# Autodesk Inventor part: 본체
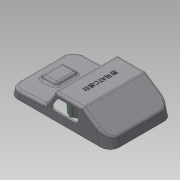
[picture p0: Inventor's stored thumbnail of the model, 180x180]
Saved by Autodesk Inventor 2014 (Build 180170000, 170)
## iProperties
Created: 2015-05
Part Number: 본체
Material: Generic
Document SubType Name: Modeling
Designer: Administrator
Density: 1 g/cm^3
Appearance: Default
Author: Administrator
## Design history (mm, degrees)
sketch "스케치1"
  geometry: L1 (61, 0)-(-61, 0); L2 (-61, 0)-(-58.321, 10); L3 (-58.321, 10)-(-28.321, 30); L4 (-28.321, 30)-(4.842, 30); L5 (61, 0)-(58.588, 9); L6 (58.588, 9)-(16.588, 11.201); L7 (4.842, 30)-(16.588, 11.201); 2 further points
  constraints: 14 end point, 1 coincident, 1 horizontal, 1 midpoint, 1 parallel
  dimensions: "d0" = 122 distance of L1.start L1.end; "d1" = 105 deg angle of L1 L2; "d2" = 20 vertical distance of L2.end L3.end; "d3" = 30 vertical distance of L1.end L3.end; "d4" = 30 horizontal distance of L2.end L3.end; "d5" = 9 vertical distance of L1.start L5.end; "d6" = 105 deg angle of L1 L5; "d7" = 3 deg angle of L1 L6; "d8" = 42 horizontal distance of L5.end L6.end; "d9" = 125 deg angle of L6 L7
extrude "돌출1" new body sketch "스케치1" stored distance "d10" = 76; taper "d11" = 0 deg
sketch "스케치2"
  geometry: L1 (58.588, 9)-(16.588, 11.201) reference; L2 (47.588, 9.576)-(46.236, 14); L3 (27.588, 10.625)-(29.021, 14); L4 (46.236, 14)-(29.021, 14); 1 further point
  constraints: 6 end point, 2 point on line
  dimensions: "d12" = 5 vertical distance of L2.end L1.start; "d13" = 11 horizontal distance of L2.start L1.start; "d14" = 20 horizontal distance of L3.start L2.start; "d15" = 70 deg angle of L1 L3; "d16" = 70 deg angle of L1 L2; "d17" = 5 vertical distance of L1.start L3.end
extrude "돌출2" join sketch "스케치2" stored distance "d18" = 26; taper "d19" = 0 deg
fillet "모깎기1" dims "d20" = 12
fillet "모깎기2" dims "d21" = 3
fillet "모깎기3" dims "d22" = 3
fillet "모깎기4" dims "d23" = 3
sketch "스케치3" dims "d29" = 4
  geometry: L1 (64.179, 61)-(64.179, 9) reference; L2 (30.591, 73)-(0, 73) reference; 2 further points
  constraints: 1 other
  dimensions: "d24" = 50 distance from line of point (14.179, 35) L1; "d25" = 38 distance from line of point (14.179, 35) L2
feature "엠보싱1" sketch "스케치3" dims "d0" = 122, "d1" = 105 deg, "d2" = 20, "d3" = 30, "d4" = 30, "d5" = 9, "d6" = 105 deg, "d7" = 3 deg, "d8" = 42, "d9" = 125 deg, "d26" = 0.5, "d27" = 0
feature "쉘1" dims "d28" = 2
sketch "스케치4"
  geometry: A1 r 2 centre (0, 47) between (0, 45) and (0, 49); A2 r 2 centre (0, 36) between (0, 34) and (0, 38); A3 r 2 centre (0, 16) between (0, 14) and (0, 18); A4 r 2 centre (0, 5) between (0, 3) and (0, 7); 3 further points
  constraints: 8 point on circle, 4 centre point, 13 other
  dimensions: "d29" = 4 diameter of A1; "d30" = 4 diameter of A2; "d31" = 4 diameter of A3; "d32" = 4 diameter of A4; "d33" = 10 vertical distance of A2.centre point (15.788, 26); "d34" = 20 distance of A2.centre A3.centre; "d35" = 11 distance of A3.centre A4.centre; "d36" = 11 distance of A1.centre A2.centre
extrude "돌출3" join sketch "스케치4" distance "d37" = 2; taper "d38" = 0 deg
chamfer "모따기1" distance "d39" = 1; stored, may be unused: second distance "d40" = 2, angle "d41" = 45 deg
node "작업 평면1"
sketch "스케치6"
  geometry: L1 (5.723, 28.59)-(15.761, 12.526) reference; L2 (-27.412, 30)-(3.179, 30) reference; L3 (-46.036, 18.19)-(-29.076, 29.496) reference; L4 (2.951, 23.59)-(8.575, 14.59); L5 (-19.557, 25)-(0.407, 25); L6 (-22.557, 22)-(-22.557, 13); L7 (-19.557, 10)-(6.031, 10); A1 r 3 centre (0.407, 22) between (2.951, 23.59) and (0.407, 25); A2 r 3 centre (0.407, 22) between (2.951, 23.59) and (0.407, 25); A3 r 3 centre (-19.557, 22) between (-19.557, 25) and (-22.557, 22); A4 r 3 centre (-19.557, 13) between (-22.557, 13) and (-19.557, 10); A5 r 3 centre (6.031, 13) between (6.031, 10) and (8.575, 14.59); 4 further points
  constraints: 10 point on circle, 10 tangent, 8 end point, 8 point on line, 5 centre point, 3 equal radius, 2 parallel, 2 perpendicular
  dimensions: "d80" = 5 distance between parallel lines of L5 L2; "d81" = 5 distance between parallel lines of L1 L4; "d82" = 3 radius of A1; "d83" = 34 distance of point (-22.557, 10) point (11.443, 10); "d84" = 15 distance of point (-22.557, 10) point (-22.557, 25); "d85" = 3 radius of A3
sketch "스케치7"
  geometry: L1 (27.412, 27)-(44.372, 15.694) reference; L2 (-3.179, 27)-(27.412, 27) reference; L3 (-13.217, 10.936)-(-3.179, 27) reference; L4 (-46.805, 6.613)-(-17.991, 8.124) reference; L5 (-48.577, 0)-(-46.805, 6.613) reference; L6 (-48.577, 0)-(48.577, 0) reference; L7 (44.372, 15.694)-(48.577, 0) reference; A1 r 6 centre (-18.305, 14.115) between (-17.991, 8.124) and (-13.217, 10.936) reference; 3 further points
  dimensions: "d79" = 122 distance of point (-60.934, 0) point (61.066, 0)
extrude "돌출5" cut sketch "스케치6" distance "d86" = 2; taper "d87" = 0 deg
sketch "스케치9"
  geometry: L1 (107.506, 64)-(107.506, 12) reference; L2 (97.153, 2)-(0, 2) reference; L3 (-10.353, 12)-(-10.353, 64) reference; L4 (0, 74)-(97.153, 74) reference; L5 (-12.423, 64)-(-12.423, 12) reference; L6 (97.153, 0)-(0, 0) reference; L7 (109.577, 12)-(109.577, 15) reference; L8 (109.577, 15)-(109.577, 19) reference; L9 (109.577, 19)-(109.577, 26) reference; L10 (109.577, 26)-(109.577, 30) reference; L11 (109.577, 30)-(109.577, 46) reference; L12 (109.577, 46)-(109.577, 50) reference; L13 (109.577, 50)-(109.577, 57) reference; L14 (109.577, 57)-(109.577, 61) reference; L15 (109.577, 61)-(109.577, 64) reference; L16 (0, 76)-(97.153, 76) reference; L17 (-11.423, 12)-(-11.423, 64); L18 (0, 75)-(97.153, 75); L19 (108.577, 64)-(108.577, 61); L20 (108.577, 61)-(108.577, 57); L21 (108.577, 57)-(108.577, 50); L22 (108.577, 50)-(108.577, 46); L23 (108.577, 46)-(108.577, 30); L24 (108.577, 30)-(108.577, 26); L25 (108.577, 26)-(108.577, 19); L26 (108.577, 19)-(108.577, 15); L27 (108.577, 15)-(108.577, 12); L28 (97.153, 1)-(0, 1); 9 further points; 8 other entities
  constraints: 24 end point, 7 parallel, 28 other
  dimensions: "d88" = 1 distance between parallel lines of L6 L28
extrude "돌출6" join sketch "스케치9" distance "d89" = 1; taper "d90" = 0 deg
node "작업 평면2"
sketch "스케치10"
  geometry: C1 r 3 at (-40, 0); C2 r 3 at (0, -22); C3 r 3 at (0, 22); C4 r 3 at (40, 0); 1 further point
  constraints: 4 centre point, 2 horizontal alignment, 2 vertical alignment
  dimensions: "d92" = 6 diameter of C1; "d93" = 6 diameter of C2; "d94" = 6 diameter of C3; "d95" = 6 diameter of C4; "d96" = 22 vertical distance of C3.centre C1.centre; "d97" = 22 vertical distance of C2.centre C1.centre; "d98" = 40 distance of point (0, 0) C4.centre; "d99" = 40 distance of point (0, 0) C1.centre
extrude "돌출7" join sketch "스케치10" stored distance "d100" = 1; taper "d101" = 0 deg
sketch "스케치11"
  geometry: L1 (-45, 21)-(-35, 21); L2 (-35, 21)-(-35, 23); L3 (-35, 23)-(-45, 23); L4 (-45, 23)-(-45, 21); L5 (-45, 21)-(-35, 23); L6 (-35, 21)-(-45, 23); L7 (-5, 45)-(5, 45); L8 (5, 45)-(5, 43); L9 (5, 43)-(-5, 43); L10 (-5, 43)-(-5, 45); L11 (-5, 45)-(5, 43); L12 (5, 45)-(-5, 43); L13 (45, 21)-(35, 21); L14 (35, 21)-(35, 23); L15 (35, 23)-(45, 23); L16 (45, 23)-(45, 21); L17 (45, 21)-(35, 23); L18 (35, 21)-(45, 23); L19 (5, -1)-(-5, -1); L20 (-5, -1)-(-5, 1); L21 (-5, 1)-(5, 1); L22 (5, 1)-(5, -1); L23 (5, -1)-(-5, 1); L24 (-5, -1)-(5, 1); C1 r 3 at (0, 0) reference; C2 r 3 at (0, 44) reference; C3 r 3 at (40, 22) reference; C4 r 3 at (-40, 22) reference; 1 further point
  constraints: 48 end point, 8 midpoint, 8 parallel, 4 horizontal, 4 perpendicular
  dimensions: "d102" = 10 distance of L3.end L2.end; "d103" = 2 distance of L2.end L1.end; "d104" = 10 distance of L8.end L9.end; "d105" = 2 distance of L7.end L8.end; "d106" = 10 distance of L14.end L15.end; "d107" = 2 distance of L13.end L14.end; "d108" = 10 distance of L20.end L21.end; "d109" = 2 distance of L19.end L20.end
extrude "돌출8" join sketch "스케치11" stored distance "d110" = 1; taper "d111" = 2.5 deg
sketch "스케치13"
  geometry: L1 (-5, -21)-(-2.828, -21) reference; L2 (-5, -23)-(-5, -21) reference; L3 (-2.828, -23)-(-5, -23) reference; L4 (5, -23)-(2.828, -23) reference; L5 (5, -21)-(5, -23) reference; L6 (2.828, -21)-(5, -21) reference; A1 r 3 centre (0, -22) between (-2.828, -23) and (2.828, -23) reference; A2 r 3 centre (0, -22) between (2.828, -21) and (-2.828, -21) reference; 1 further point
sketch "스케치14"
  geometry: L1 (-1.06, 24.299)-(0.973, 27.556) reference; L2 (0, 0)-(-1.06, 24.299) reference; L3 (0, 0)-(2.172, 0) reference; 3 further points; 1 other entity
  constraints: 2 other
node "솔리드1"
mirror "대칭1"
node "투영된 루프1"
node "투영된 루프2"
other parameters: "d61" = -38, "d91" = 0
